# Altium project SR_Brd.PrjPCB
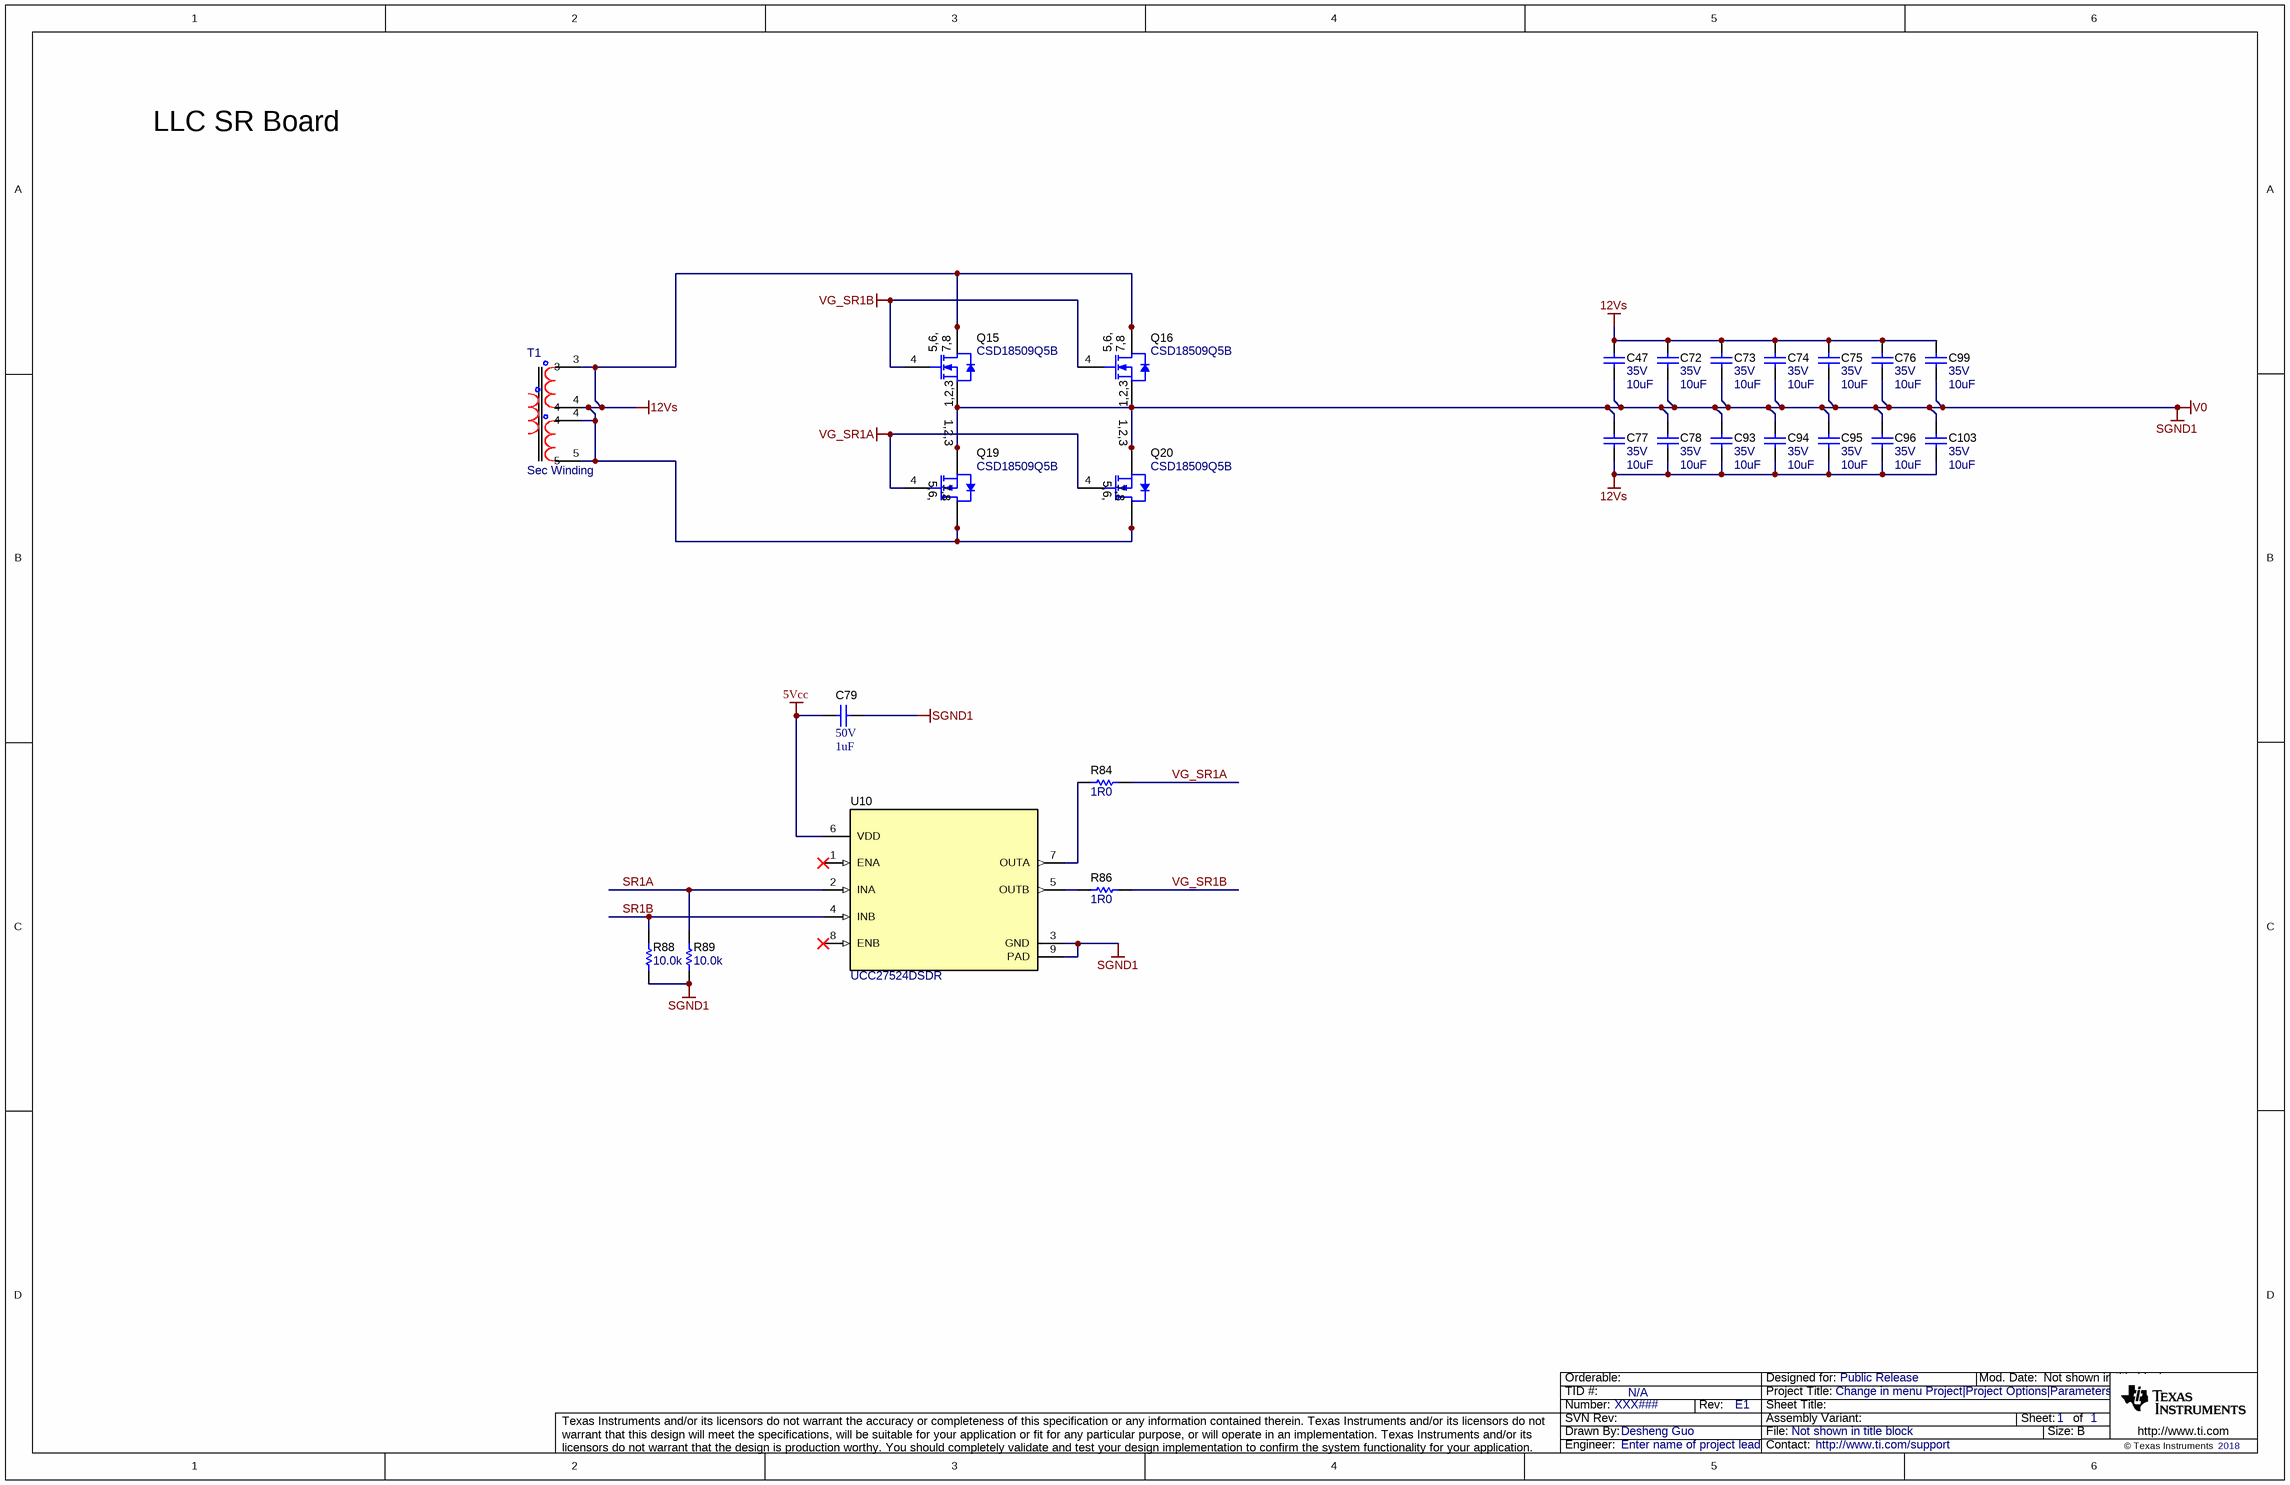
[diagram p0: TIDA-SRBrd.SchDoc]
CopyrightYear: 2018; PCB_Layout: Who did the Layout?; PCB_Rev: E1; PRJ_Customer: Public Release; PRJ_Engineer: Enter name of project lead; PRJ_Number: XXX###; PRJ_Title: Change in menu Project|Project Options|Parameters; SCH_Rev: E1; TechSupport: http://www.ti.com/support; TID: N/A
1 sheet, 25 parts. Net scope: global (net labels, ports and power ports of the same name join across sheets).
Board file: SRBrd_PQ32-1-V2.2.PcbDoc

## Sheet TIDA-SRBrd.SchDoc
size 431 x 279 mm; Date: Not shown in title block; ApprovedBy: Not shown in title block; CheckedBy: Not shown in title block; Author: Desheng Guo; CompanyName: Not shown in title block; DrawnBy: Desheng Guo; Engineer: Desheng Guo; Organization: Not shown in title block; Address1: Not shown in title block; Address2: Not shown in title block; Address3: Not shown in title block; Address4: Not shown in title block; DocumentNumber: 1; Revision: Use project parameter SCH_Rev; SheetNumber: 1; SheetTotal: 1; PageSetup: Record=PageOptions¦CenterHorizontal=True¦CenterVertical=True¦PrintScale=1.00¦XCorrection=1.00¦YCorrection=1.00¦PrintKind=0¦BorderSize=5000000¦LeftOffset=0¦BottomOffset=0¦Orientation=2¦PaperLength=1000¦PaperWidth=1000¦Scale=100¦PaperSource=15¦PrintQuality=600¦MediaType=1¦DitherType=10¦PaperKind=Letter¦PrintScaleMode=1

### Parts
C47  VDC_V: 35V  ValueDisplayed: 10uF  [1206_190]  (hidden comment: GMK316AB7106KL-TR)
C72  VDC_V: 35V  ValueDisplayed: 10uF  [1206_190]  (hidden comment: GMK316AB7106KL-TR)
C73  VDC_V: 35V  ValueDisplayed: 10uF  [1206_190]  (hidden comment: GMK316AB7106KL-TR)
C74  VDC_V: 35V  ValueDisplayed: 10uF  [1206_190]  (hidden comment: GMK316AB7106KL-TR)
C75  VDC_V: 35V  ValueDisplayed: 10uF  [1206_190]  (hidden comment: GMK316AB7106KL-TR)
C76  VDC_V: 35V  ValueDisplayed: 10uF  [1206_190]  (hidden comment: GMK316AB7106KL-TR)
C77  VDC_V: 35V  ValueDisplayed: 10uF  [1206_190]  (hidden comment: GMK316AB7106KL-TR)
C78  VDC_V: 35V  ValueDisplayed: 10uF  [1206_190]  (hidden comment: GMK316AB7106KL-TR)
C79  VDC_V: 50V  ValueDisplayed: 1uF  [0603]  (hidden comment: UMK107AB7105KA-T)
C93  VDC_V: 35V  ValueDisplayed: 10uF  [1206_190]  (hidden comment: GMK316AB7106KL-TR)
C94  VDC_V: 35V  ValueDisplayed: 10uF  [1206_190]  (hidden comment: GMK316AB7106KL-TR)
C95  VDC_V: 35V  ValueDisplayed: 10uF  [1206_190]  (hidden comment: GMK316AB7106KL-TR)
C96  VDC_V: 35V  ValueDisplayed: 10uF  [1206_190]  (hidden comment: GMK316AB7106KL-TR)
C99  VDC_V: 35V  ValueDisplayed: 10uF  [1206_190]  (hidden comment: GMK316AB7106KL-TR)
C103  VDC_V: 35V  ValueDisplayed: 10uF  [1206_190]  (hidden comment: GMK316AB7106KL-TR)
Q15  CSD18509Q5B  [DNK0008A]  (no BOM)
Q16  CSD18509Q5B  [DNK0008A]
Q19  CSD18509Q5B  [DNK0008A]  (no BOM)
Q20  CSD18509Q5B  [DNK0008A]
R84  ValueDisplayed: 1R0  [0603]  (hidden comment: ERJ-3RQF2R2V)
R86  ValueDisplayed: 1R0  [0603]  (hidden comment: ERJ-3RQF2R2V)
R88  ValueDisplayed: 10.0k  [0603]  (hidden comment: ERJ-3EKF1002V)
R89  ValueDisplayed: 10.0k  [0603]  (hidden comment: ERJ-3EKF1002V)
T1  Sec Winding  [PQ3233-1000-400V12V-1]  (graphical)
U10  UCC27524DSDR  [DSD0008D]

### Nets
5Vcc: C79.2 U10.6(VDD)
12Vs: C47.1 C72.1 C73.1 C74.1 C75.1 C76.1 C77.2 C78.2 C93.2 C94.2 C95.2 C96.2 C99.1 C103.2 Q15.5(D) Q15.6(D) Q15.7(D) Q15.8(D) Q15.9(D) Q16.5(D) Q16.6(D) Q16.7(D) Q16.8(D) Q16.9(D) Q19.5(D) Q19.6(D) Q19.7(D) Q19.8(D) Q19.9(D) Q20.5(D) Q20.6(D) Q20.7(D) Q20.8(D) Q20.9(D) T1.3 T1.4 T1.5
SGND1: C47.2 C72.2 C73.2 C74.2 C75.2 C76.2 C77.1 C78.1 C79.1 C93.1 C94.1 C95.1 C96.1 C99.2 C103.1 Q15.1(S) Q15.2(S) Q15.3(S) Q16.1(S) Q16.2(S) Q16.3(S) Q19.1(S) Q19.2(S) Q19.3(S) Q20.1(S) Q20.2(S) Q20.3(S) R88.1 R89.1 U10.3(GND) U10.9(PAD)  [also labelled V0]
VG_SR1A: Q19.4(G) Q20.4(G) R84.2
VG_SR1B: Q15.4(G) Q16.4(G) R86.2
SR1A: R89.2 U10.2(INA)
SR1B: R88.2 U10.4(INB)
NetR84_1: R84.1 U10.7(OUTA)
NetR86_1: R86.1 U10.5(OUTB)

Not connected (* = marked no-connect by the designer): U10 1(ENA)* 8(ENB)*

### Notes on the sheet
- LLC SR Board

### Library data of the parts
C47 C72-C78 C93-C96 C99 C103 = CMP-0008822-2: CAP, CERM, 10 uF, 35 V, +/- 10%, X7R, 1206_190; Manufacturer: Taiyo Yuden; TaMin_C: -55°C; Polarized: N; SizeAreaWB_mm2: 10.92; Value1: Unknown; U/M: EA; Value: 10uF; TaMax_C: 125°C; SizeZ_mm: 1.9; SizeX_mm: 3.2; SizeY_mm: 1.6; Cap_Case: 1206; SizeArea_mm2: 5.12; Cap_F: 10µF; AEC Category: Q200
C79 = CMP-0007508-5: CAP, CERM, 1 uF, 50 V, +/- 10%, X7R, 0603; Manufacturer: Taiyo Yuden; TaMin_C: -55°C; Polarized: N; SizeAreaWB_mm2: 4.68; Value1: Unknown; U/M: EA; Value: 1uF; TaMax_C: 125°C; SizeZ_mm: 1; SizeX_mm: 1.6; SizeY_mm: 0.8; SizeArea_mm2: 1.28; Cap_F: 1µF; AEC Category: Q200
Q15 Q16 Q19 Q20 = CMP-0000709-2: MOSFET, N-CH, 40 V, 100 A, DNK0008A (VSON-CLIP-8); Alternate Manufacturer: None; Manufacturer: Texas Instruments; SizeZ_mm: 1; ChType: N; Value2: 150 nC; Value1: 0.001; VdsMax_V: 40V; SizeX_mm: 6; SizeY_mm: 5; Vgs_V: 20V; Value: 40V; Rdson45_ohm: 1.7m; SizeArea_mm2: 30; AEC Category: Q101; IdsMax_A: 100A; SizeAreaWB_mm2: 56; U/M: EA; QgTyp_nC: 150
R84 = CMP-0022711-2: RES, 2.20, 1%, 0.1 W, 0603; Manufacturer: Panasonic; Power_W: 100mW; TempCo: 200 ppm/C; Value_Code: 2R20; U/M: EA; Value: 2.20; Res_ohm: 2.2; SizeX_mm: 1.6; SizeY_mm: 0.8; SizeZ_mm: 1; Value2: 0.1W; SizeArea_mm2: 1.28; AEC Category: Q200
R86 = CMP-0022711-2: RES, 1ohm 1%, 0.1 W, 0603; Manufacturer: Panasonic; Power_W: 100mW; TempCo: 200 ppm/C; Value_Code: 1R; U/M: EA; Value: 2.20; Res_ohm: 1; SizeX_mm: 1.6; SizeY_mm: 0.8; Value2: 0.1W; SizeArea_mm2: 1.28; AEC Category: Q200
R88 R89 = CMP-0022684-3: RES, 10.0 k, 1%, 0.1 W, 0603; Manufacturer: Panasonic; Power_W: 100mW; TempCo: 100 ppm/C; Value_Code: 10k0; U/M: EA; Value: 10.0k; EIA_Code: E96; Res_ohm: 10k; SizeX_mm: 1.6; SizeY_mm: 0.8; SizeZ_mm: 1; Value2: 0.1W; SizeArea_mm2: 1.28; VDC_V: 75V; AEC Category: Q200
T1 = Trans_sec: Manufacturer: HUAIHUA YAXIN ELECTRONICS CO., LTD; SymbolCreator: Use LDAP id; SymbolVersion: use current date i.e. 2008-05-20
U10 = CMP-0066952-1: Dual, 5A, High-Speed Low-Side Power MOSFET Driver, DSD0008D (WSON-8); Alternate PartNumber: UCC27524DSDT; Alternate Manufacturer: Texas Instruments; SizeAreaWB_mm2: 16.0; U/M: EA; SizeZ_mm: 0.8; SizeX_mm: 3.0; SizeArea_mm2: 9.0; CompType: IC

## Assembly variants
001: not fitted FID1 FID2 FID3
